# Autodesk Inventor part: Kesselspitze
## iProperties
Created: 2007-03
Part Number: Kesselspitze
Document SubType Name: Modeling
Designer: Benno
Manufacturer: Standard
Standards Organization: Custom
Author: Benno
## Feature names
1. Erhebung1
2. Extrusion1
3. Fase1 [Chamfer]
